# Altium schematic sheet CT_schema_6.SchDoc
size 421 x 246 mm
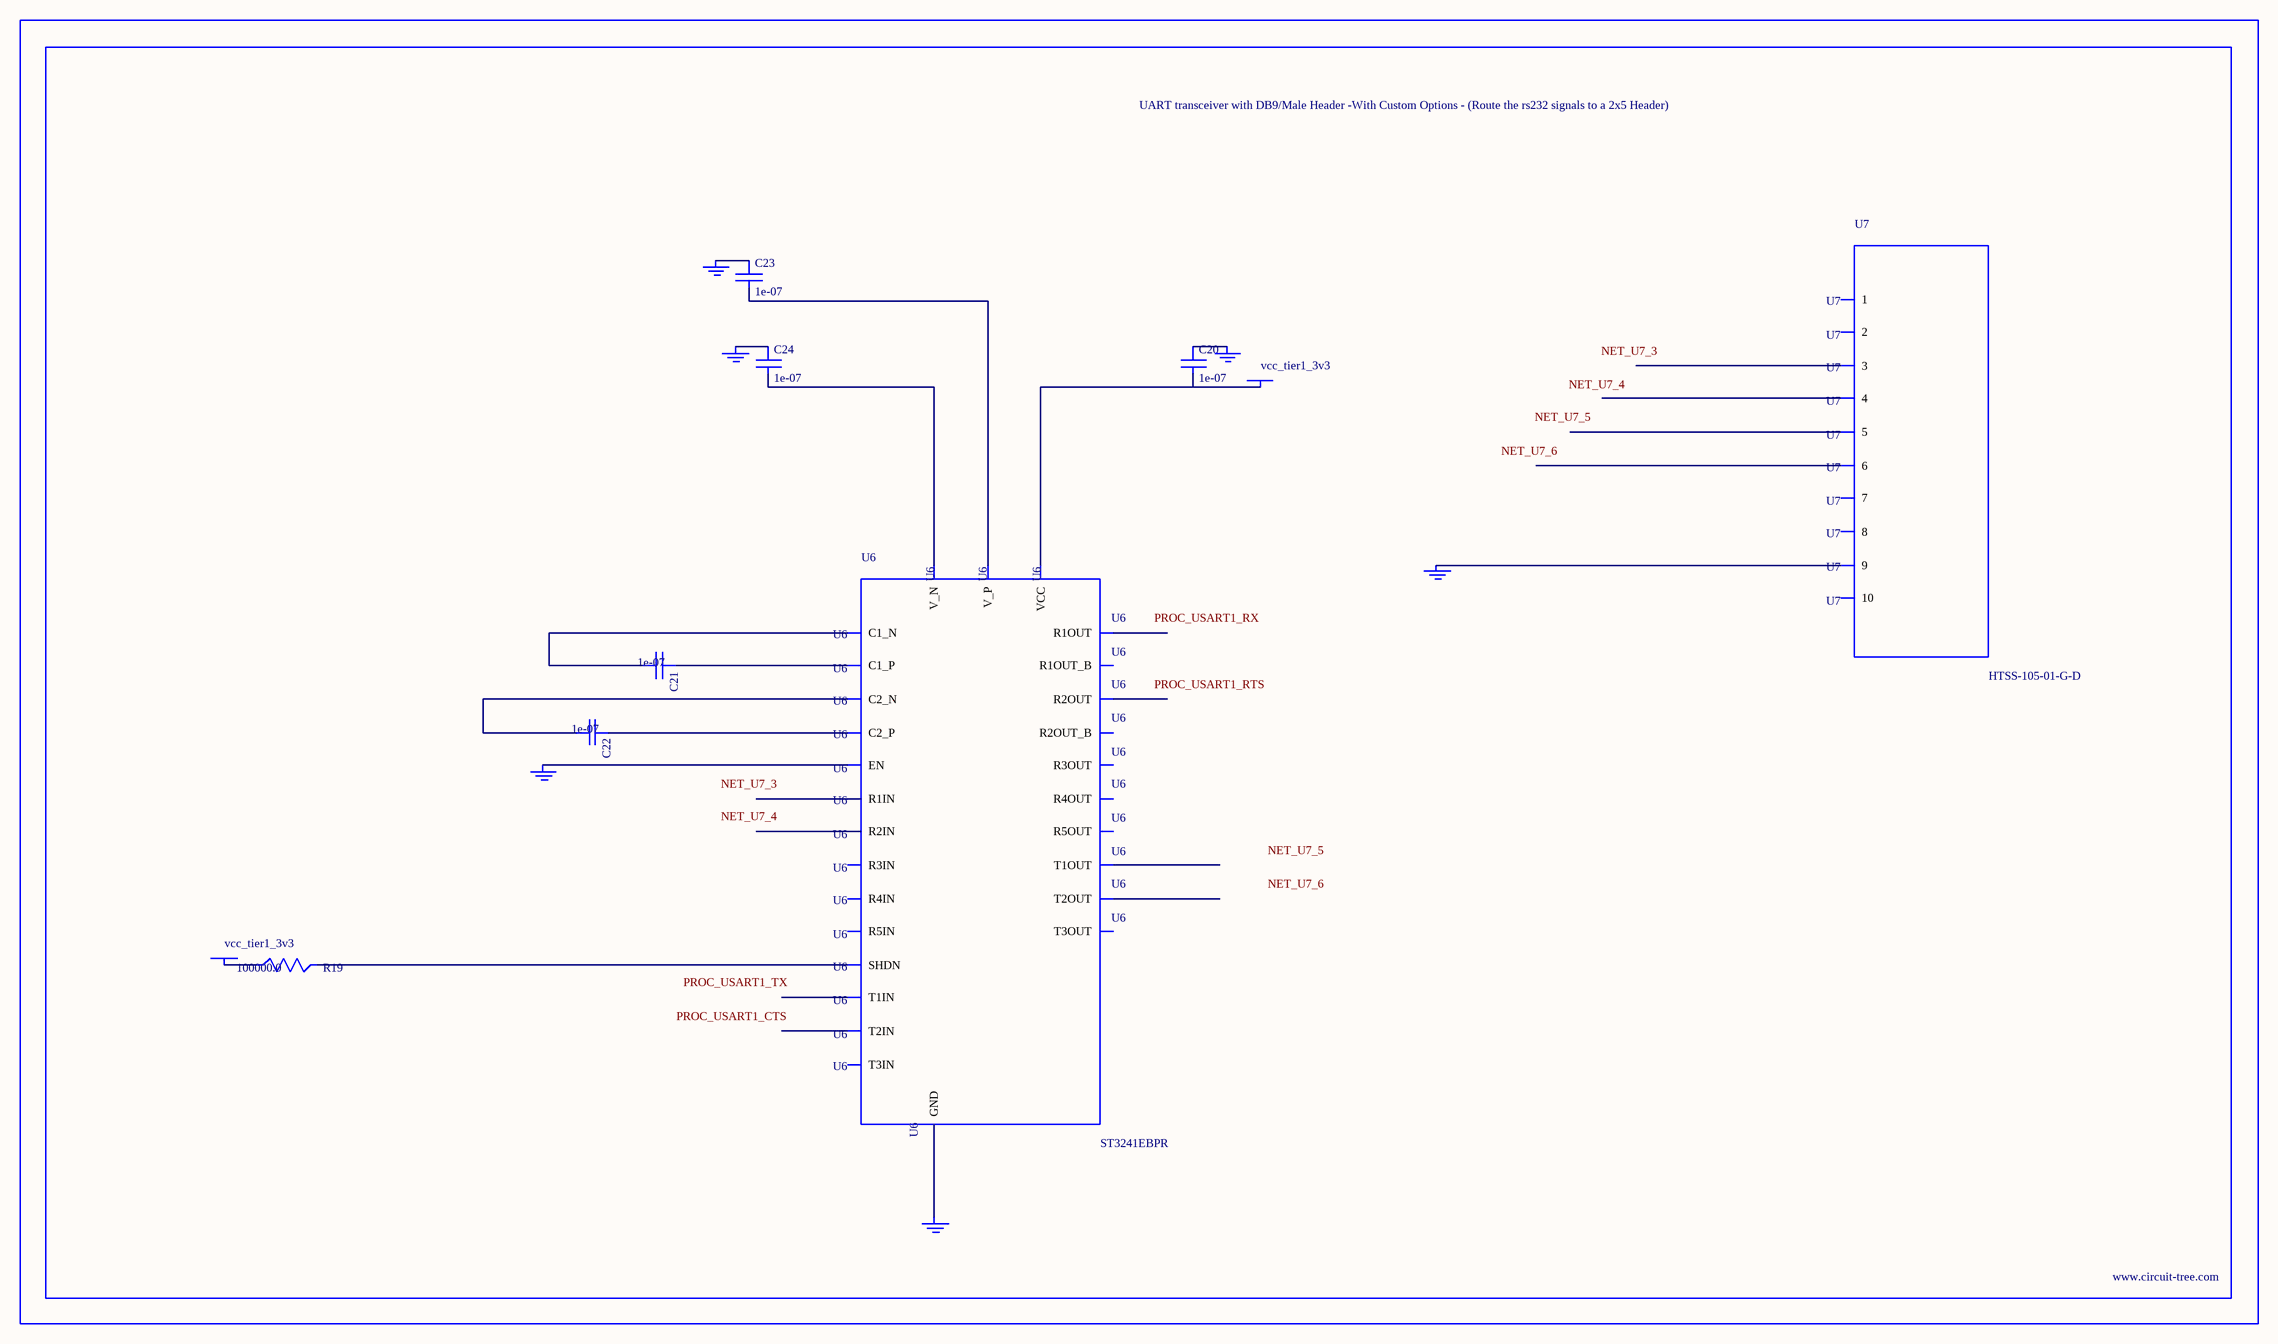
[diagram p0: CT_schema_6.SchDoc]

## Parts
BORDER5  (no value)
C20  1e-07  [C0402]
C21  1e-07  [C0402]
C22  1e-07  [C0402]
C23  1e-07  [C0402]
C24  1e-07  [C0402]
GND_INSTANCE_5_0  (no value)
GND_INSTANCE_5_1  (no value)
GND_INSTANCE_5_2  (no value)
GND_INSTANCE_5_3  (no value)
GND_INSTANCE_5_4  (no value)
GND_INSTANCE_5_5  (no value)
POWER_INSTANCE_5_0  vcc_tier1_3v3
POWER_INSTANCE_5_1  vcc_tier1_3v3
R19  100000.0  [R0603]
U6  ST3241EBPR  [SSOP-28]
U7  HTSS-105-01-G-D  [HTSS-105-01-G-D]

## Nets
NetC20_1: C20.1 GND_INSTANCE_5_2.0(GND)
NetC20_2: C20.2 POWER_INSTANCE_5_1.0(PWR) U6.26(VCC)
NetC21_1: C21.1 U6.28(C1_P)
NetC21_2: C21.2 U6.24(C1_N)
NetC22_1: C22.1 U6.1(C2_P)
NetC22_2: C22.2 U6.2(C2_N)
NetC23_1: C23.1 GND_INSTANCE_5_3.0(GND)
NetC23_2: C23.2 U6.27(V_P)
NetC24_1: C24.1 GND_INSTANCE_5_0.0(GND)
NetC24_2: C24.2 U6.3(V_N)
NetGND_INSTANCE_5_1_0: GND_INSTANCE_5_1.0(GND) U6.23(EN)
NetGND_INSTANCE_5_4_0: GND_INSTANCE_5_4.0(GND) U6.25(GND)
NetGND_INSTANCE_5_5_0: GND_INSTANCE_5_5.0(GND) U7.9
NetPOWER_INSTANCE_5_0_0: POWER_INSTANCE_5_0.0(PWR) R19.1
NetR19_2: R19.2 U6.22(SHDN)

Not connected (* = marked no-connect by the designer): U6 4(R1IN) 5(R2IN) 6(R3IN) 7(R4IN) 8(R5IN) 9(T1OUT) 10(T2OUT) 11(T3OUT) 12(T3IN) 13(T2IN) 14(T1IN) 15(R5OUT) 16(R4OUT) 17(R3OUT) 18(R2OUT) 19(R1OUT) 20(R2OUT_B) 21(R1OUT_B); U7 1 2 3 4 5 6 7 8 10

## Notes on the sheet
- Labels drawn without touching a wire or pin: NET_U7_3, NET_U7_4, NET_U7_5, NET_U7_6, PROC_USART1_CTS, PROC_USART1_RTS, PROC_USART1_RX, PROC_USART1_TX

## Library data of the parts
BORDER5 = BORDER_PAGE5
C20-C24 = C0402C104K3RACTU
GND_INSTANCE_5_0-GND_INSTANCE_5_5 = GND
POWER_INSTANCE_5_0 POWER_INSTANCE_5_1 = PWR
R19 = RC0603JR-07100KL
